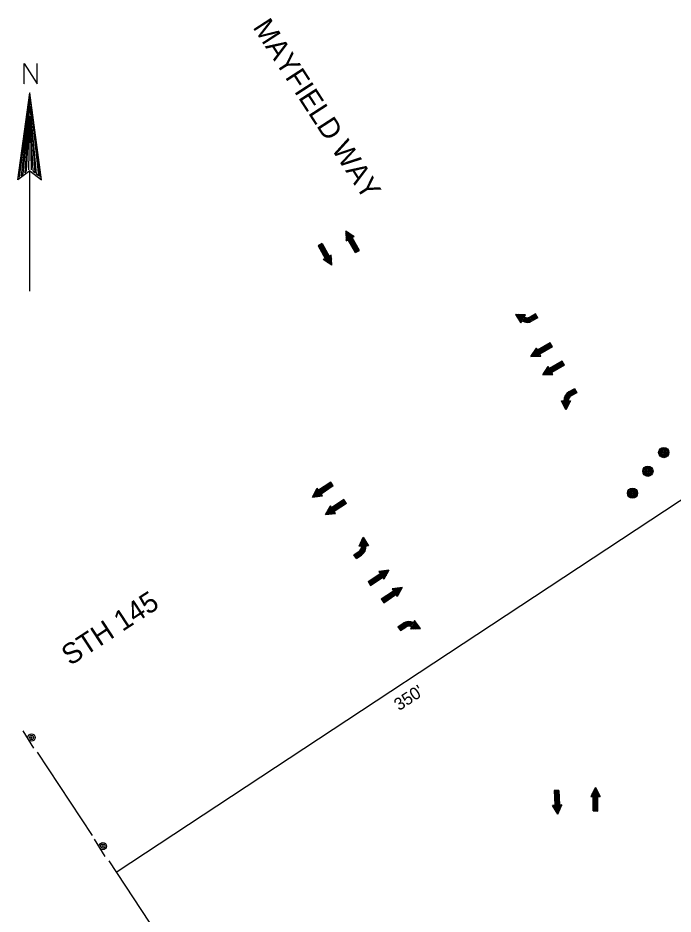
# Model space of a CAD drawing. Extents: x 358662 to 361839, y 132407 to 133741.
# Drawn here: x 359764.4 to 360084, y 132934 to 133370.9 of the extents above; entities that cross this region are included whole.
import ezdxf

# ---------------------------------------------------------------- set-up
doc = ezdxf.new("R2010")
doc.units = 0
for name, color, linetype in [('E_BLD_Dash', 7, 'Continuous'), ('E_BLD_Footing', 7, 'Continuous'), ('P_FTMS_LaneLbl', 7, 'Continuous')]:
    doc.layers.add(name, color=color, linetype=linetype)

msp = doc.modelspace()

# ---------------------------------------------------------------- linework, layer by layer
at = {"layer": 'E_BLD_Dash'}
for p, q in [((359772.26, 133014.94), (359766.94, 133023.41)), ((359807.05, 132962.02), (359801.73, 132970.49))]:
    msp.add_line(p, q, dxfattribs=at)
for centre, radius in [((360079.5, 133158.98), 2.5), ((360079.5, 133158.98), 2), ((360079.5, 133158.98), 1.5), ((360079.5, 133158.98), 1), ((360079.5, 133158.98), 0.5), ((360079.5, 133158.98), 0.25), ((360071.77, 133149.88), 2.5), ((360071.77, 133149.88), 2), ((360071.77, 133149.88), 1.5), ((360071.77, 133149.88), 1), ((360071.77, 133149.88), 0.5), ((360071.77, 133149.88), 0.25), ((360064.26, 133139.19), 2.5), ((360064.26, 133139.19), 2), ((360064.26, 133139.19), 1.5), ((360064.26, 133139.19), 1), ((360064.26, 133139.19), 0.5), ((360064.26, 133139.19), 0.25), ((359771.1, 133020.08), 1.75), ((359771.1, 133020.08), 1), ((359771.1, 133020.08), 0.25), ((359805.89, 132967.16), 1.75), ((359805.89, 132967.16), 1), ((359805.89, 132967.16), 0.25)]:
    msp.add_circle(centre, radius, dxfattribs=at)
at = {"layer": 'E_BLD_Footing'}
for p, q in [((359924.4, 133267.05), (359924.6, 133262.13)), ((359924.4, 133267.05), (359928.53, 133264.33)), ((359929.85, 133256.9), (359924.41, 133266.62)), ((359929.45, 133256.68), (359924.46, 133265.63)), ((359930.24, 133257.12), (359924.87, 133266.74)), ((359930.63, 133257.34), (359925.68, 133266.2)), ((359927.54, 133263.8), (359926.49, 133265.67)), ((359927.93, 133264.02), (359927.31, 133265.13)), ((359912.83, 133260.93), (359910.87, 133259.83)), ((359911.85, 133260.38), (359911.85, 133260.38)), ((359912.04, 133260.49), (359917.48, 133250.76)), ((359912.44, 133260.71), (359917.44, 133251.76)), ((359912.83, 133260.93), (359916.3, 133254.71)), ((359925.57, 133262.7), (359924.5, 133264.63)), ((359925.18, 133262.48), (359924.54, 133263.63)), ((359924.79, 133262.26), (359924.58, 133262.63)), ((359924.6, 133262.13), (359928.53, 133264.33)), ((359929.06, 133256.46), (359925.59, 133262.68)), ((359931.03, 133257.56), (359927.55, 133263.77)), ((359928.32, 133264.24), (359928.12, 133264.59)), ((359910.87, 133259.83), (359914.34, 133253.61)), ((359911.26, 133260.05), (359916.21, 133251.19)), ((359911.65, 133260.27), (359917.03, 133250.65)), ((359929.06, 133256.46), (359931.03, 133257.56)), ((359930.04, 133257.01), (359930.04, 133257.01)), ((359917.29, 133255.26), (359913.36, 133253.06)), ((359917.5, 133250.34), (359913.36, 133253.06)), ((359913.57, 133253.15), (359913.77, 133252.79)), ((359913.96, 133253.37), (359914.58, 133252.26)), ((359914.35, 133253.59), (359915.4, 133251.72)), ((359916.32, 133254.69), (359917.39, 133252.76)), ((359916.71, 133254.91), (359917.35, 133253.76)), ((359917.1, 133255.13), (359917.31, 133254.76)), ((359917.5, 133250.34), (359917.29, 133255.26)), ((360012.04, 133226.07), (360007.11, 133226.34)), ((360007.11, 133226.34), (360009.78, 133222.18)), ((360010.79, 133223.93), (360007.38, 133225.93)), ((360011.02, 133224.32), (360007.6, 133226.32)), ((360011.25, 133224.71), (360008.59, 133226.26)), ((360011.47, 133225.1), (360009.58, 133226.21)), ((360011.7, 133225.49), (360010.56, 133226.15)), ((360011.47, 133225.1), (360012.04, 133226.07)), ((360011.93, 133225.88), (360011.55, 133226.1)), ((360016.94, 133226.62), (360014.25, 133225.09)), ((360017.17, 133226.23), (360014.48, 133224.7)), ((360017.39, 133225.84), (360014.7, 133224.3)), ((360017.61, 133225.45), (360014.92, 133223.91)), ((360018.06, 133224.67), (360016.94, 133226.62)), ((360017.5, 133225.64), (360017.5, 133225.64)), ((360010.57, 133223.54), (360007.91, 133225.09)), ((360010.35, 133223.15), (360008.45, 133224.26)), ((360010.12, 133222.76), (360008.98, 133223.43)), ((360009.89, 133222.37), (360009.51, 133222.6)), ((360009.78, 133222.18), (360010.35, 133223.15)), ((360017.83, 133225.06), (360015.15, 133223.52)), ((360018.06, 133224.67), (360015.37, 133223.13)), ((360024.07, 133212.51), (360017.9, 133208.96)), ((360025.19, 133210.56), (360024.07, 133212.51)), ((360014.67, 133205.77), (360017.34, 133209.94)), ((360024.52, 133211.73), (360014.97, 133206.24)), ((360024.75, 133211.34), (360015.09, 133205.79)), ((360024.3, 133212.12), (360015.49, 133207.06)), ((360017.88, 133208.95), (360016.02, 133207.88)), ((360024.97, 133210.95), (360016.09, 133205.84)), ((360017.65, 133209.34), (360016.55, 133208.7)), ((360017.43, 133209.73), (360017.07, 133209.53)), ((360019.58, 133206.04), (360017.34, 133209.94)), ((360025.19, 133210.56), (360019.02, 133207.01)), ((360024.63, 133211.54), (360024.63, 133211.54)), ((360014.67, 133205.77), (360019.58, 133206.04)), ((360019, 133207), (360017.08, 133205.9)), ((360019.22, 133206.61), (360018.08, 133205.95)), ((360019.45, 133206.22), (360019.08, 133206.01)), ((360029.91, 133203.6), (360023.74, 133200.05)), ((360031.03, 133201.65), (360029.91, 133203.6)), ((360020.5, 133196.85), (360023.17, 133201.02)), ((360030.36, 133202.82), (360020.81, 133197.33)), ((360030.58, 133202.43), (360020.93, 133196.88)), ((360030.14, 133203.21), (360021.33, 133198.15)), ((360023.71, 133200.04), (360021.86, 133198.97)), ((360030.81, 133202.04), (360021.92, 133196.93)), ((360023.49, 133200.43), (360022.38, 133199.79)), ((360023.27, 133200.82), (360022.91, 133200.61)), ((360025.42, 133197.12), (360023.17, 133201.02)), ((360031.03, 133201.65), (360024.86, 133198.1)), ((360030.47, 133202.62), (360030.47, 133202.62)), ((360020.5, 133196.85), (360025.42, 133197.12)), ((360024.84, 133198.09), (360022.92, 133196.99)), ((360025.06, 133197.7), (360023.92, 133197.04)), ((360025.28, 133197.31), (360024.92, 133197.1)), ((360035.91, 133190.09), (360033.22, 133188.56)), ((360036.13, 133189.7), (360033.44, 133188.17)), ((360036.35, 133189.31), (360033.66, 133187.78)), ((360036.58, 133188.91), (360033.88, 133187.39)), ((360036.8, 133188.52), (360034.11, 133186.99)), ((360037.02, 133188.13), (360034.33, 133186.6)), ((360035.91, 133190.09), (360037.02, 133188.13)), ((360036.46, 133189.11), (360036.46, 133189.11)), ((360031.77, 133179.82), (360029.55, 133184.24)), ((360029.55, 133184.24), (360030.67, 133184.23)), ((360029.77, 133184.23), (360029.77, 133183.8)), ((360030.22, 133184.23), (360030.21, 133182.91)), ((360030.67, 133184.23), (360030.66, 133182.03)), ((360031.12, 133184.22), (360031.1, 133181.14)), ((360031.57, 133184.21), (360031.54, 133180.26)), ((360034.05, 133184.2), (360031.77, 133179.82)), ((360032.02, 133184.21), (360031.99, 133180.26)), ((360032.47, 133184.21), (360032.45, 133181.13)), ((360032.92, 133184.2), (360032.91, 133182.01)), ((360032.92, 133184.2), (360034.05, 133184.2)), ((360033.37, 133184.2), (360033.36, 133182.88)), ((360033.82, 133184.2), (360033.82, 133183.76)), ((359917.52, 133143.85), (359908.35, 133137.75)), ((359917.77, 133143.48), (359908.5, 133137.31)), ((359917.27, 133144.23), (359908.82, 133138.6)), ((359918.02, 133143.1), (359909.49, 133137.43)), ((359917.02, 133144.6), (359911.09, 133140.66)), ((359918.27, 133142.73), (359912.34, 133138.78)), ((359918.27, 133142.73), (359917.02, 133144.6)), ((359917.65, 133143.66), (359917.65, 133143.66)), ((359908.08, 133137.26), (359910.47, 133141.59)), ((359911.07, 133140.64), (359909.29, 133139.46)), ((359910.82, 133141.02), (359909.76, 133140.31)), ((359910.57, 133141.39), (359910.23, 133141.16)), ((359912.96, 133137.84), (359910.47, 133141.59)), ((359912.32, 133138.77), (359910.48, 133137.55)), ((359912.57, 133138.39), (359911.47, 133137.67)), ((359912.82, 133138.02), (359912.46, 133137.78)), ((359908.08, 133137.26), (359912.96, 133137.84)), ((359923.93, 133135.34), (359914.75, 133129.23)), ((359924.18, 133134.96), (359914.9, 133128.79)), ((359923.68, 133135.71), (359915.22, 133130.09)), ((359924.43, 133134.59), (359915.89, 133128.91)), ((359923.43, 133136.09), (359917.5, 133132.14)), ((359924.68, 133134.21), (359918.75, 133130.27)), ((359924.68, 133134.21), (359923.43, 133136.09)), ((359924.05, 133135.15), (359924.05, 133135.15)), ((359914.48, 133128.74), (359916.87, 133133.08)), ((359914.48, 133128.74), (359919.37, 133129.33)), ((359917.48, 133132.13), (359915.69, 133130.94)), ((359917.23, 133132.5), (359916.17, 133131.8)), ((359916.98, 133132.88), (359916.64, 133132.65)), ((359919.37, 133129.33), (359916.87, 133133.08)), ((359918.72, 133130.25), (359916.89, 133129.03)), ((359918.97, 133129.88), (359917.88, 133129.15)), ((359919.22, 133129.5), (359918.87, 133129.27)), ((359930.97, 133113.29), (359932.93, 133117.82)), ((359932.54, 133113.39), (359932.34, 133116.46)), ((359932.99, 133113.42), (359932.73, 133117.36)), ((359932.93, 133117.82), (359935.46, 133113.57)), ((359933.44, 133113.45), (359933.18, 133117.39)), ((359933.88, 133113.48), (359933.68, 133116.54)), ((359932.09, 133113.36), (359930.97, 133113.29)), ((359931.19, 133113.3), (359931.16, 133113.74)), ((359931.64, 133113.33), (359931.55, 133114.65)), ((359932.09, 133113.36), (359931.95, 133115.55)), ((359934.33, 133113.5), (359934.19, 133115.69)), ((359935.46, 133113.57), (359934.33, 133113.5)), ((359934.78, 133113.53), (359934.7, 133114.84)), ((359935.23, 133113.56), (359935.2, 133113.99)), ((359928.28, 133109.15), (359930.86, 133110.87)), ((359929.53, 133107.28), (359928.28, 133109.15)), ((359928.53, 133108.77), (359931.11, 133110.49)), ((359928.78, 133108.4), (359931.36, 133110.12)), ((359928.91, 133108.21), (359928.91, 133108.21)), ((359929.03, 133108.03), (359931.61, 133109.74)), ((359929.28, 133107.65), (359931.86, 133109.37)), ((359929.53, 133107.28), (359932.11, 133108.99)), ((359935.22, 133096.09), (359941.13, 133100.08)), ((359935.47, 133095.72), (359943.97, 133101.45)), ((359935.73, 133095.35), (359944.96, 133101.58)), ((359935.98, 133094.98), (359945.11, 133101.14)), ((359936.23, 133094.6), (359944.65, 133100.28)), ((359945.38, 133101.63), (359940.5, 133101.01)), ((359940.5, 133101.01), (359943.02, 133097.28)), ((359940.65, 133100.84), (359941, 133101.08)), ((359940.9, 133100.47), (359941.99, 133101.2)), ((359941.15, 133100.09), (359942.98, 133101.33)), ((359942.41, 133098.23), (359944.18, 133099.43)), ((359945.38, 133101.63), (359943.02, 133097.28)), ((359935.22, 133096.09), (359936.48, 133094.23)), ((359935.85, 133095.16), (359935.85, 133095.16)), ((359936.48, 133094.23), (359942.39, 133098.21)), ((359942.66, 133097.85), (359943.72, 133098.57)), ((359942.91, 133097.48), (359943.25, 133097.71)), ((359941.68, 133087.62), (359947.59, 133091.61)), ((359941.94, 133087.25), (359950.43, 133092.98)), ((359942.19, 133086.88), (359951.42, 133093.11)), ((359942.44, 133086.5), (359951.57, 133092.67)), ((359942.69, 133086.13), (359951.11, 133091.81)), ((359951.84, 133093.16), (359946.96, 133092.54)), ((359946.96, 133092.54), (359949.48, 133088.81)), ((359947.11, 133092.37), (359947.46, 133092.6)), ((359947.36, 133092), (359948.45, 133092.73)), ((359947.61, 133091.62), (359949.44, 133092.86)), ((359948.87, 133089.76), (359950.64, 133090.95)), ((359949.12, 133089.38), (359950.18, 133090.1)), ((359951.84, 133093.16), (359949.48, 133088.81)), ((359941.68, 133087.62), (359942.94, 133085.76)), ((359942.31, 133086.69), (359942.31, 133086.69)), ((359942.94, 133085.76), (359948.85, 133089.74)), ((359949.37, 133089.01), (359949.71, 133089.24)), ((359957.89, 133077.14), (359957.4, 133076.13)), ((359957.79, 133076.94), (359958.19, 133076.75)), ((359960.85, 133073.18), (359957.89, 133077.14)), ((359949.81, 133074.07), (359952.38, 133075.79)), ((359949.81, 133074.07), (359951.07, 133072.2)), ((359950.06, 133073.69), (359952.64, 133075.42)), ((359950.32, 133073.32), (359952.89, 133075.04)), ((359950.44, 133073.13), (359950.44, 133073.13)), ((359950.57, 133072.95), (359953.14, 133074.67)), ((359950.82, 133072.57), (359953.39, 133074.3)), ((359951.07, 133072.2), (359953.64, 133073.92)), ((359956.41, 133074.11), (359955.92, 133073.1)), ((359955.92, 133073.1), (359960.85, 133073.18)), ((359956.02, 133073.3), (359956.41, 133073.11)), ((359956.21, 133073.7), (359957.4, 133073.12)), ((359956.41, 133074.11), (359958.38, 133073.14)), ((359956.61, 133074.51), (359959.37, 133073.16)), ((359956.81, 133074.92), (359960.36, 133073.17)), ((359957.01, 133075.32), (359960.56, 133073.58)), ((359957.21, 133075.72), (359959.96, 133074.37)), ((359957.4, 133076.13), (359959.37, 133075.16)), ((359957.59, 133076.53), (359958.78, 133075.95)), ((360028.25, 132994.32), (360026, 132994.19)), ((360026, 132994.19), (360026.41, 132987.08)), ((360026.45, 132994.22), (360027.03, 132984.08)), ((360026.9, 132994.25), (360027.53, 132983.24)), ((360027.12, 132994.26), (360027.12, 132994.26)), ((360027.35, 132994.27), (360027.99, 132983.15)), ((360027.8, 132994.3), (360028.38, 132984.07)), ((360028.25, 132994.32), (360028.65, 132987.21)), ((360046.21, 132995.78), (360043.97, 132991.4)), ((360045.5, 132984.26), (360045.56, 132994.51)), ((360045.95, 132984.26), (360046.02, 132995.4)), ((360046.21, 132995.78), (360048.47, 132991.37)), ((360046.4, 132984.26), (360046.47, 132995.28)), ((360046.85, 132984.25), (360046.91, 132994.41)), ((360043.97, 132991.4), (360048.47, 132991.37)), ((360044.19, 132991.42), (360044.2, 132991.84)), ((360044.64, 132991.42), (360044.65, 132992.73)), ((360045.05, 132984.27), (360045.09, 132991.39)), ((360045.09, 132991.41), (360045.11, 132993.62)), ((360047.3, 132984.25), (360047.34, 132991.37)), ((360047.34, 132991.4), (360047.36, 132993.54)), ((360047.79, 132991.4), (360047.8, 132992.67)), ((360048.24, 132991.39), (360048.25, 132991.8)), ((360029.78, 132987.27), (360025.28, 132987.02)), ((360027.82, 132982.76), (360025.28, 132987.02)), ((360025.51, 132987.01), (360025.53, 132986.6)), ((360025.96, 132987.03), (360026.03, 132985.76)), ((360026.41, 132987.06), (360026.53, 132984.92)), ((360027.82, 132982.76), (360029.78, 132987.27)), ((360028.66, 132987.19), (360028.78, 132984.98)), ((360029.11, 132987.21), (360029.18, 132985.9)), ((360029.55, 132987.24), (360029.58, 132986.82)), ((360045.05, 132984.27), (360047.3, 132984.25)), ((360046.17, 132984.26), (360046.17, 132984.26))]:
    msp.add_line(p, q, dxfattribs=at)
for centre, radius, start, end in [((360012.88, 133227.5), 5.03, 239.7257, 299.729), ((360012.88, 133227.5), 4.58, 239.7257, 299.729), ((360012.88, 133227.5), 4.13, 239.7257, 299.729), ((360012.88, 133227.5), 3.68, 239.7257, 299.729), ((360012.88, 133227.5), 3.23, 239.7257, 299.729), ((360012.88, 133227.5), 2.78, 239.7257, 299.729), ((360035.7, 133184.19), 5.03, 119.6052, 179.6085), ((360035.7, 133184.19), 4.58, 119.6052, 179.6085), ((360035.7, 133184.19), 4.13, 119.6052, 179.6085), ((360035.7, 133184.19), 3.68, 119.6052, 179.6085), ((360035.7, 133184.19), 3.23, 119.6052, 179.6085), ((360035.7, 133184.19), 2.78, 119.6052, 179.6085), ((359929.31, 133113.18), 2.78, 303.7165, 3.7198), ((359929.31, 133113.18), 3.23, 303.7165, 3.7198), ((359929.31, 133113.18), 3.68, 303.7165, 3.7198), ((359929.31, 133113.18), 4.13, 303.7165, 3.7198), ((359929.31, 133113.18), 4.58, 303.7165, 3.7198), ((359929.31, 133113.18), 5.03, 303.7165, 3.7198), ((359955.19, 133071.61), 5.03, 63.837, 123.8402), ((359955.19, 133071.61), 4.58, 63.837, 123.8402), ((359955.19, 133071.61), 4.13, 63.837, 123.8402), ((359955.19, 133071.61), 3.68, 63.837, 123.8402), ((359955.19, 133071.61), 3.23, 63.837, 123.8402), ((359955.19, 133071.61), 2.78, 63.837, 123.8402)]:
    msp.add_arc(centre, radius, start, end, dxfattribs=at)
at = {"layer": 'P_FTMS_LaneLbl'}
for p, q in [((359767.57, 133348.41), (359767.57, 133348.41)), ((359767.5, 133338.57), (359767.5, 133338.57)), ((359770.2, 133334.41), (359770.07, 133334.09)), ((359770.2, 133334.41), (359770.2, 133334.41)), ((359765.59, 133300.48), (359765.59, 133300.48)), ((359765.82, 133300.84), (359765.82, 133300.84)), ((359774.56, 133300.84), (359774.56, 133300.84)), ((359774.8, 133300.48), (359774.8, 133300.48)), ((359770.2, 133237.66), (359770.2, 133296.34)), ((359770.2, 133237.66), (359770.2, 133296.32)), ((359764.44, 133292), (359764.44, 133292)), ((359764.73, 133292.45), (359764.73, 133292.45)), ((359775.66, 133292.45), (359775.66, 133292.45)), ((359775.95, 133292), (359775.95, 133292)), ((359812.42, 132954.44), (360102.61, 133145.62)), ((359773.83, 133013.01), (359800.65, 132972.3)), ((359808.73, 132960.03), (359835.69, 132919.11))]:
    msp.add_line(p, q, dxfattribs=at)
for points in [[(359767.48, 133338.81), (359767.48, 133348.65), (359773.91, 133338.81), (359773.91, 133348.65)], [(359770.2, 133296.34), (359764.44, 133292), (359770.2, 133334.41)], [(359765.23, 133293.32), (359770.21, 133331.54), (359766.1, 133293.96), (359767.01, 133294.71), (359770.17, 133327.79), (359767.81, 133295.42), (359768.69, 133296.25), (359770.17, 133323.04), (359769.67, 133296.8)], [(359770.2, 133296.34), (359775.95, 133292), (359770.2, 133334.41)], [(359775.34, 133293.32), (359770.36, 133331.54), (359774.46, 133293.96), (359773.55, 133294.71), (359770.4, 133327.79), (359772.75, 133295.42), (359771.88, 133296.25), (359770.4, 133323.04), (359770.89, 133296.8)]]:
    msp.add_lwpolyline(points, dxfattribs=at)

# ---------------------------------------------------------------- texts
for s, height, rotation, p in [('MAYFIELD WAY', 10, 302.8889, (359878.76, 133366.36)), ('STH 145', 10, 33.1867, (359789.93, 133054.84)), ("350'", 6, 33.0497, (359950.39, 133032.92))]:
    msp.add_text(s, height=height, rotation=rotation, dxfattribs=at).set_placement(p)

doc.saveas('drawing.dxf')
